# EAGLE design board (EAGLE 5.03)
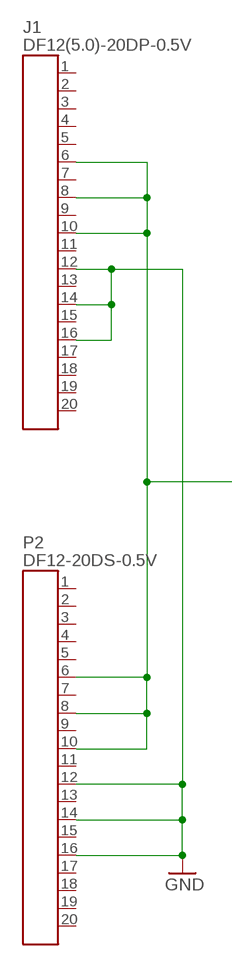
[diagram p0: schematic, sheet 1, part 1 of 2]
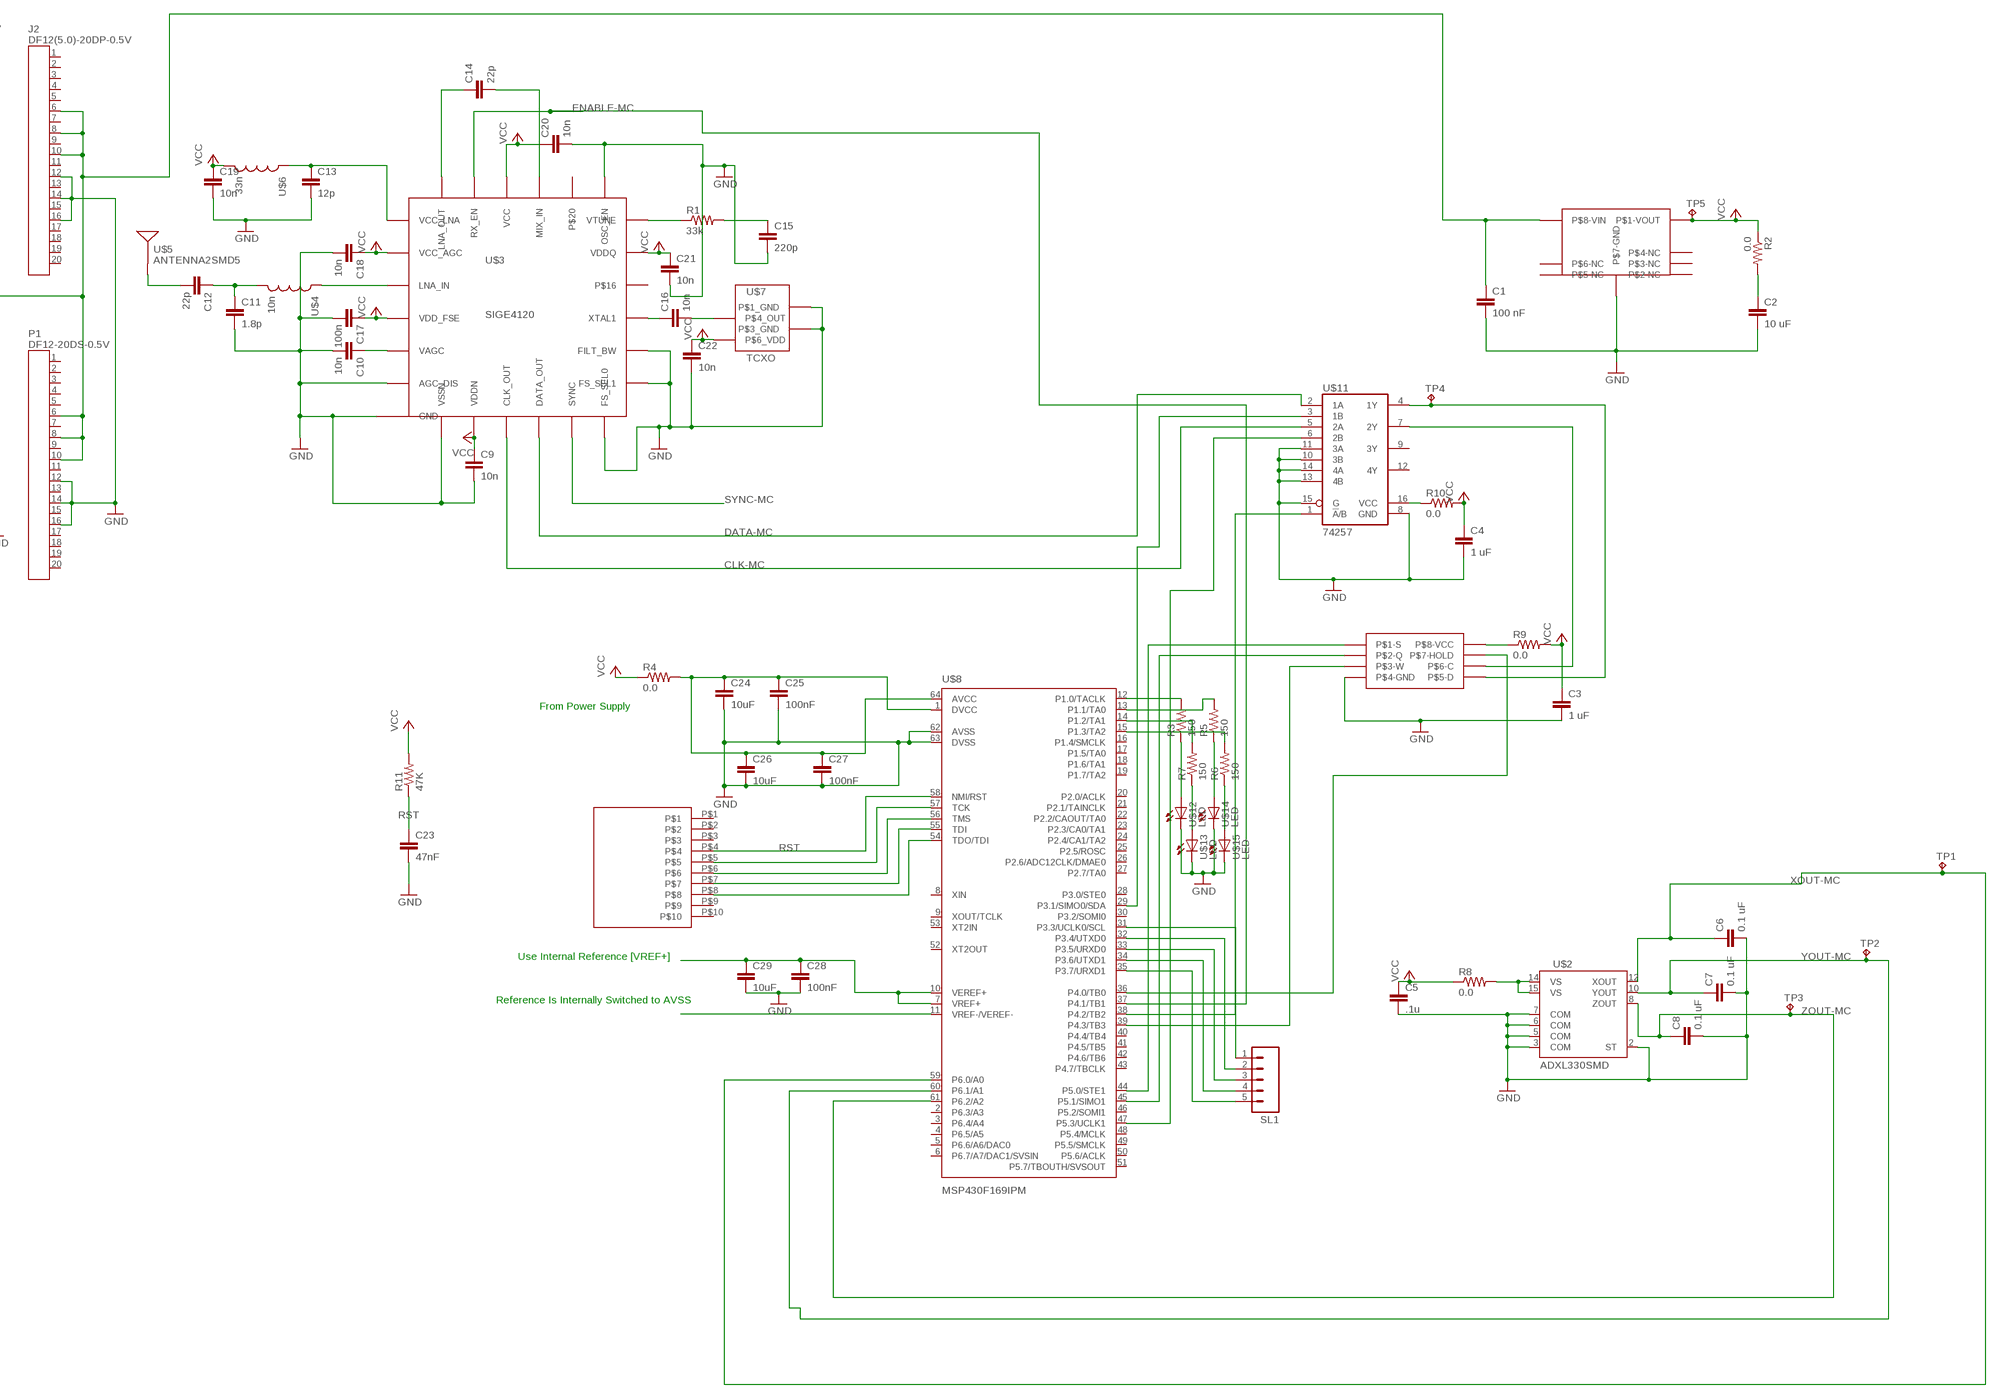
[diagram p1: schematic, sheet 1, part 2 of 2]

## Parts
C1  100 nF  CAP0402  [C0402]
C2  10 uF  CAP0402  [C0402]
C3  1 uF  CAP0402  [C0402]
C4  1 uF  CAP0402  [C0402]
C5  .1u  CAP0402  [C0402]
C6  0.1 uF  CAP0402  [C0402]
C7  0.1 uF  CAP0402  [C0402]
C8  0.1 uF  CAP0402  [C0402]
C9  10n  CAP0402  [C0402]
C10  10n  CAP0402  [C0402]
C11  1.8p  CAP0402  [C0402]
C12  22p  CAP0402  [C0402]
C13  12p  CAP0402  [C0402]
C14  22p  CAP0402  [C0402]
C15  220p  CAP0402  [C0402]
C16  10n  CAP0402  [C0402]
C17  100n  CAP0402  [C0402]
C18  10n  CAP0402  [C0402]
C19  10n  CAP0402  [C0402]
C20  10n  CAP0402  [C0402]
C21  10n  CAP0402  [C0402]
C22  10n  CAP0402  [C0402]
C23  47nF  CAP0402  [C0402]
C24  10uF  CAP0402  [C0402]
C25  100nF  CAP0402  [C0402]
C26  10uF  CAP0402  [C0402]
C27  100nF  CAP0402  [C0402]
C28  100nF  CAP0402  [C0402]
C29  10uF  CAP0402  [C0402]
J1  DF12(5.0)-20DP-0.5V  [DF12(XX)-20DP-0.5V]
J2  DF12(5.0)-20DP-0.5V  [DF12(XX)-20DP-0.5V]
P1  DF12-20DS-0.5V  [DF12-20DS-0.5V]
P2  DF12-20DS-0.5V  [DF12-20DS-0.5V]
R1  33k  RESISTOR0402  [C0402]
R2  0.0  RESISTOR  [0805]
R3  150  RESISTOR0402  [C0402]
R4  0.0  RESISTOR  [0805]
R5  150  RESISTOR0402  [C0402]
R6  150  RESISTOR0402  [C0402]
R7  150  RESISTOR0402  [C0402]
R8  0.0  RESISTOR  [0805]
R9  0.0  RESISTOR  [0805]
R10  0.0  RESISTOR  [0805]
R11  47K  RESISTOR0402  [C0402]
SL1  M05  [1X05]
TP1  TPTP09SQ  [TP09SQ]
TP2  TPTP09SQ  [TP09SQ]
TP3  TPTP09SQ  [TP09SQ]
TP4  TPTP09SQ  [TP09SQ]
TP5  TPTP09SQ  [TP09SQ]
U$1  FH12A-10S-0.5SH(55)  [FH12A-10S-0.5SH(55)]
U$2  ADXL330SMD  [LFCSP-16]
U$3  SIGE4120  [SIGE4120]
U$4  10n  INDUCTOR0402  [C0402]
U$5  ANTENNA2SMD5  [ANTENNA-CHIP5]
U$6  33n  INDUCTOR0402  [C0402]
U$7  TCXO  [TXCO]
U$8  MSP430F169IPM  [S-PQFP64-G64]
U$9  M25P128  [VDFPN8]
U$10  LM2936  [8-SOIC]
U$11  74257  [16]
U$12  LED  [LED0402]
U$13  LED  [LED0402]
U$14  LED  [LED0402]
U$15  LED  [LED0402]

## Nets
CLK-MC: U$3.CLK_OUT U$11.5(2A)
DATA-MC: U$3.DATA_OUT U$11.2(1A)
ENABLE-MC: U$3.RX_EN U$8.37(P4.1/TB1)
GND: C1.2 C2.2 C3.2 C4.2 C5.2 C6.2 C7.2 C8.2 C9.2 C10.2 C11.2 C13.2 C15.2 C17.2 C18.2 C19.2 C20.2 C21.2 C22.2 C23.2 C24.2 C25.2 C26.2 C27.2 C28.2 C29.2 J1.12 J1.14 J1.16 J2.12 J2.14 J2.16 P1.12 P1.14 P1.16 P2.12 P2.14 P2.16 U$2.2(ST) U$2.3(COM) U$2.5(COM) U$2.6(COM) U$2.7(COM) U$3.AGC_DIS U$3.FILT_BW U$3.FS_SEL0 U$3.FS_SEL1 U$3.GND U$3.OSC_EN U$3.VSSN U$7.P$1_GND U$7.P$3_GND U$8.62(AVSS) U$8.63(DVSS) U$9.P$4(P$4-GND) U$10.P$7-GND U$11.8(GND) U$11.10(3B) U$11.11(3A) U$11.13(4B) U$11.14(4A) U$11.15(G) U$12.P$2 U$13.P$2 U$14.P$2 U$15.P$2
N$1: U$8.36(P4.0/TB0) U$9.P$7(P$7-HOLD)
N$2: C28.1 C29.1 U$8.7(VREF+) U$8.10(VEREF+)
N$3: U$1.P$8 U$8.54(TDO/TDI)
N$4: SL1.1 U$8.31(P3.3/UCLK0/SCL)
N$5: C10.1 U$3.VAGC
N$6: SL1.2 U$8.32(P3.4/UTXD0)
N$7: U$3.LNA_IN U$4.1
N$8: C11.1 C12.1 U$4.2
N$9: C12.2 U$5.FEED(SIGNAL)
N$10: C13.1 U$3.VCC_LNA U$6.1
N$11: C14.1 U$3.LNA_OUT
N$12: C14.2 U$3.MIX_IN
N$13: R1.1 U$3.VTUNE
N$14: C15.1 R1.2
N$15: C16.1 U$3.XTAL1
N$16: C16.2 U$7.P$4_OUTPUT(P$4_OUT)
N$17: C1.1 J1.6 J1.8 J1.10 J2.6 J2.8 J2.10 P1.6 P1.8 P1.10 P2.6 P2.8 P2.10 U$10.P$8-VIN
N$18: C2.1 R2.2
N$19: U$8.11(VREF-/VEREF-)
N$20: SL1.3 U$8.33(P3.5/URXD0)
N$21: C24.1 C25.1 C26.1 C27.1 R4.2 U$8.1(DVCC) U$8.64(AVCC)
N$22: SL1.4 U$8.34(P3.6/UTXD1)
N$23: SL1.5 U$8.35(P3.7/URXD1)
N$24: U$8.45(P5.1/SIMO1) U$9.P$2(P$2-Q)
N$25: U$8.44(P5.0/STE1) U$9.P$1(P$1-S)
N$26: U$8.38(P4.2/TB2) U$11.1(!A!/B)
N$27: R9.1 U$9.P$8(P$8-VCC)
N$28: TP4.TP U$9.P$5(P$5-D) U$11.4(1Y)
N$29: U$8.47(P5.3/UCLK1) U$11.6(2B)
N$30: U$8.29(P3.1/SIMO0/SDA) U$11.3(1B)
N$31: U$1.P$7 U$8.55(TDI)
N$32: U$1.P$6 U$8.56(TMS)
N$33: U$1.P$5 U$8.57(TCK)
N$34: U$8.39(P4.3/TB3) U$9.P$3(P$3-W)
N$35: R3.2 U$8.12(P1.0/TACLK)
N$36: U$9.P$6(P$6-C) U$11.7(2Y)
N$37: R3.1 U$12.P$1
N$38: R5.2 U$8.13(P1.1/TA0)
N$39: R5.1 U$14.P$1
N$40: R7.2 U$8.14(P1.2/TA1)
N$41: R7.1 U$13.P$1
N$42: R6.2 U$8.15(P1.3/TA2)
N$43: R6.1 U$15.P$1
N$44: R8.2 U$2.14(VS) U$2.15(VS)
N$45: R10.1 U$11.16(VCC)
RST: C23.1 R11.1 U$1.P$4 U$8.58(NMI/RST)
SYNC-MC: U$3.SYNC
VCC: C3.1 C4.1 C5.1 C9.1 C17.1 C18.1 C19.1 C20.1 C21.1 C22.1 R2.1 R4.1 R8.1 R9.2 R10.2 R11.2 TP5.TP U$3.VCC U$3.VCC_AGC U$3.VDD_FSE U$3.VDDN U$3.VDDQ U$6.2 U$7.P$6_VDD U$10.P$1-VOUT
XOUT-MC: C6.1 TP1.TP U$2.12(XOUT) U$8.59(P6.0/A0)
YOUT-MC: C7.1 TP2.TP U$2.10(YOUT) U$8.60(P6.1/A1)
ZOUT-MC: C8.1 TP3.TP U$2.8(ZOUT) U$8.61(P6.2/A2)
Unconnected: J1.1 J1.2 J1.3 J1.4 J1.5 J1.7 J1.9 J1.11 J1.13 J1.15 J1.17 J1.18 J1.19 J1.20 J2.1 J2.2 J2.3 J2.4 J2.5 J2.7 J2.9 J2.11 J2.13 J2.15 J2.17 J2.18 J2.19 J2.20 P1.1 P1.2 P1.3 P1.4 P1.5 P1.7 P1.9 P1.11 P1.13 P1.15 P1.17 P1.18 P1.19 P1.20 P2.1 P2.2 P2.3 P2.4 P2.5 P2.7 P2.9 P2.11 P2.13 P2.15 P2.17 P2.18 P2.19 P2.20 U$1.P$1 U$1.P$2 U$1.P$3 U$1.P$9 U$1.P$10 U$3.P$16 U$3.P$20 U$8.2(P6.3/A3) U$8.3(P6.4/A4) U$8.4(P6.5/A5) U$8.5(P6.6/A6/DAC0) U$8.6(P6.7/A7/DAC1/SVSIN) U$8.8(XIN) U$8.9(XOUT/TCLK) U$8.16(P1.4/SMCLK) U$8.17(P1.5/TA0) U$8.18(P1.6/TA1) U$8.19(P1.7/TA2) U$8.20(P2.0/ACLK) U$8.21(P2.1/TAINCLK) U$8.22(P2.2/CAOUT/TA0) U$8.23(P2.3/CA0/TA1) U$8.24(P2.4/CA1/TA2) U$8.25(P2.5/ROSC) U$8.26(P2.6/ADC12CLK/DMAE0) U$8.27(P2.7/TA0) U$8.28(P3.0/STE0) U$8.30(P3.2/SOMI0) U$8.40(P4.4/TB4) U$8.41(P4.5/TB5) U$8.42(P4.6/TB6) U$8.43(P4.7/TBCLK) U$8.46(P5.2/SOMI1) U$8.48(P5.4/MCLK) U$8.49(P5.5/SMCLK) U$8.50(P5.6/ACLK) U$8.51(P5.7/TBOUTH/SVSOUT) U$8.52(XT2OUT) U$8.53(XT2IN) U$10.P$2-NC U$10.P$3-NC U$10.P$4-NC U$10.P$5-NC U$10.P$6-NC U$11.9(3Y) U$11.12(4Y)

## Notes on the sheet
- From Power Supply
- Use Internal Reference [VREF+]
- Reference Is Internally Switched to AVSS

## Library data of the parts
C1-C29 = SparkFun:CAP: Capacitor
J1 J2 = Hirose Connectors:DF12(5.0)-20DP-0.5V: Connector, Header, board-board, 20-pin. Dual Row, 5mm stack height, 0.5mm Pitch (Hirose)
P1 P2 = Hirose Connectors:DF12-20DS-0.5V: Connector, Receptacle, board-board, 20-pin. Dual Row, 3.5 to 5mm stack height, 0.5mm Pitch (Hirose)
R1-R11 = SparkFun:RESISTOR: Resistor
SL1 = SparkFun-3-2-07:M05: Header 5 Standard 5-pin 0.1" header. Use with straight break away headers (SKU : PType-HD), right angle break away headers (PType-HD-RightAngle), swiss pins (PType-30F), machine pins (PType-MP), and female headers (PType-FH). Molex polarized connector foot print use with SKU : Con-Hdr with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
TP1-TP5 = testpad:TP: Test pad
U$1 = mylib:FH12A-10S-0.5SH(55)
U$2 = SparkFun:ADXL330: Triple Axis Accelerometer Analog Devices ADXL330 +/-3g 2.4V-5.25V Analog output. Spark Fun Electronics SKU : COM-00730. Center pad paste layer has been reduced to avoid shorting.
U$3 = mylib:SIGE4120
U$4 U$6 = SparkFun:INDUCTOR: Inductors
U$5 = SparkFun:ANTENNA2: Antenna
U$7 = mylib:TCXO
U$8 = msp430:MSP430F16*: Mixed Signal Microcontroller 12bit ADC, 12bit DAC, I²C, USART, no LCD
U$9 = mylib:M25P128
U$10 = lm2936a:LM2936
U$11 = mylib:74257
U$12-U$15 = mylib:LED

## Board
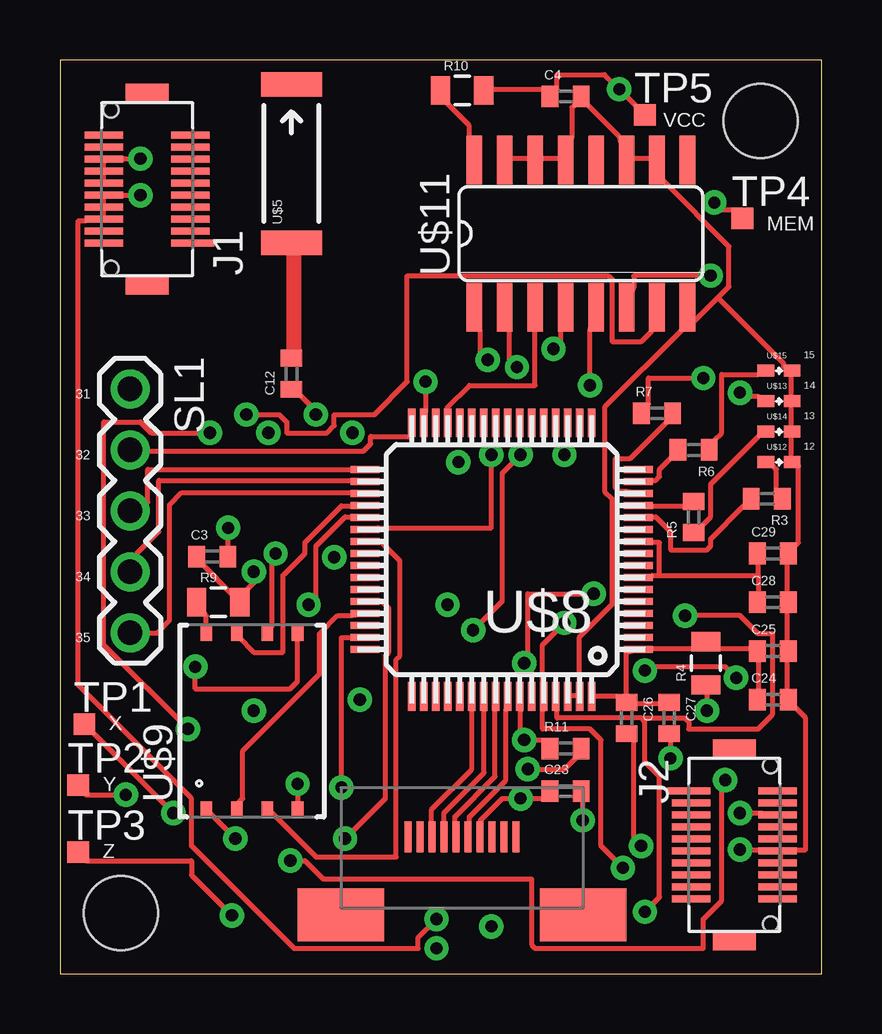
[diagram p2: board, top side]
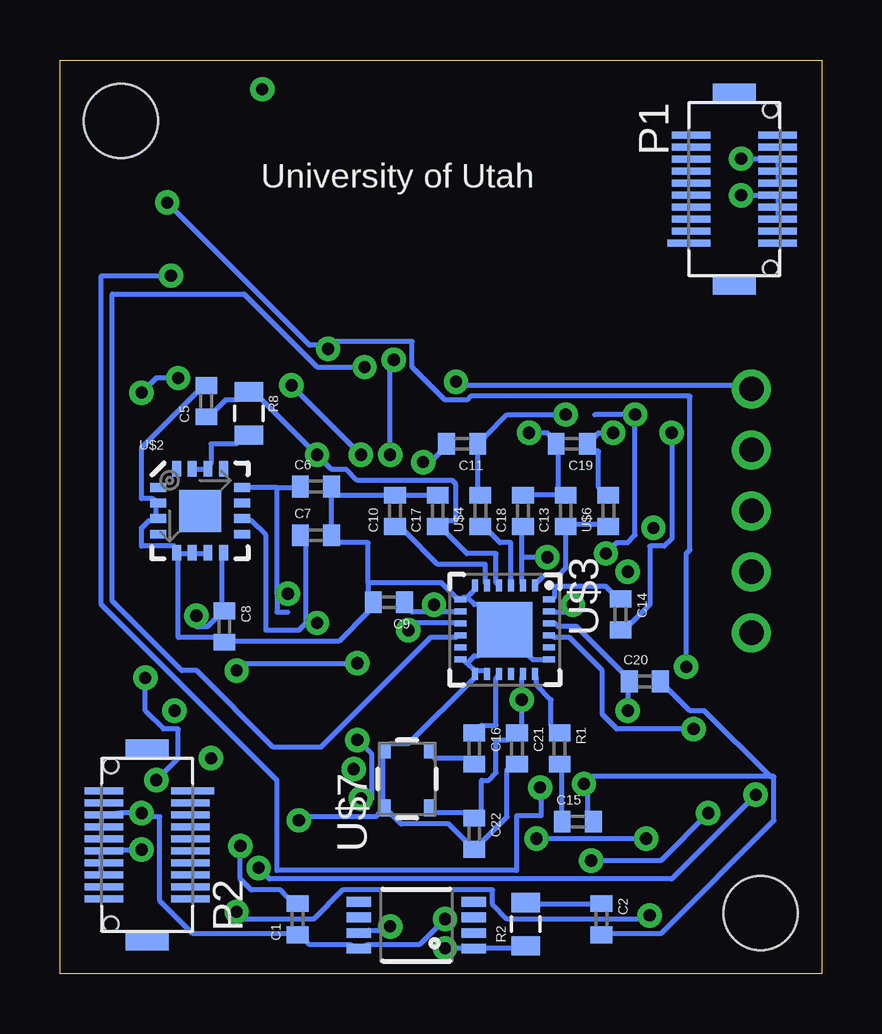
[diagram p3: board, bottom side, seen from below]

Size 31.75 x 38.1 mm. Coordinates in mm from the lower left corner, seen from the top.
Outline: 0,0 31.75,0 31.75,38.1 0,38.1 0,0
Copper layers ((1*2)+(15*16)): Top 0.035mm / dielectric 1.5mm / $gnd 0.035mm / dielectric 0.15mm / $vcc 0.035mm / dielectric 0.2mm / Bottom 0.035mm
Design rules "SparkFun *": minimum track width 8mil, minimum drill 20mil, track to track 6mil, track to pad 6mil, pad to pad 6mil, via to via 6mil, smd to smd 6mil, copper to edge 10mil, drill to drill 8mil, minimum pad ring 12mil, minimum via ring 10mil, stop-mask expansion 4mil, vias tented up to drill 25mil, thermal gap 10mil
Holes 3.1 mm at 2.54,2.54 29.21,35.56
tRestrict: 4 lines
bRestrict: 4 lines

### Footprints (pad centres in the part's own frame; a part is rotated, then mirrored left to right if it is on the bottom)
C0402 = smd 0.7 x 0.9: 1 -0.65,0; 2 0.65,0
DF12(XX)-20DP-0.5V = smd 0.3 x 1.8: 1 -2.25,-1.9 | smd 0.3 x 1.6: 2 -2.25,1.8; 3 -1.75,-1.8; 4 -1.75,1.8; 5 -1.25,-1.8; 6 -1.25,1.8; 7 -0.75,-1.8; 8 -0.75,1.8; 9 -0.25,-1.8; 10 -0.25,1.8; 11 0.25,-1.8; 12 0.25,1.8; 13 0.75,-1.8; 14 0.75,1.8; 15 1.25,-1.8; 16 1.25,1.8; 17 1.75,-1.8; 18 1.75,1.8; 19 2.25,-1.8; 20 2.25,1.8 | smd 0.8 x 1.8: T1 4,0; T2 -4,0 | hole 0.635: 3.3,1.5; -3.3,1.5
DF12-20DS-0.5V = smd 0.3 x 1.8: 1 2.25,-1.9 | smd 0.3 x 1.6: 2 2.25,1.8; 3 1.75,-1.8; 4 1.75,1.8; 5 1.25,-1.8; 6 1.25,1.8; 7 0.75,-1.8; 8 0.75,1.8; 9 0.25,-1.8; 10 0.25,1.8; 11 -0.25,-1.8; 12 -0.25,1.8; 13 -0.75,-1.8; 14 -0.75,1.8; 15 -1.25,-1.8; 16 -1.25,1.8; 17 -1.75,-1.8; 18 -1.75,1.8; 19 -2.25,-1.8; 20 -2.25,1.8 | smd 0.8 x 1.8: T1 4,0; T2 -4,0 | hole 0.635: 3.3,1.5; -3.3,1.5
0805 = smd 0.8 x 1.2: 1 -0.9,0; 2 0.9,0
1X05 = drill 1.016 round: 1 0,0; 2 2.54,0; 3 5.08,0; 4 7.62,0; 5 10.16,0
TP09SQ = smd 0.9 x 0.9: TP 0,0
FH12A-10S-0.5SH(55) = smd 0.3 x 1.3: P$1 -2.25,0; P$2 -1.75,0; P$3 -1.25,0; P$4 -0.75,0; P$5 -0.25,0; P$6 0.25,0; P$7 0.75,0; P$8 1.25,0; P$9 1.75,0; P$10 2.25,0 | smd 3.6 x 2.2: P$11 -5.05,3.25; P$12 5.05,3.25
LFCSP-16 = smd 1.75 x 1.75: 0 0,0 | smd 0.65 x 0.37: 1 -1.75,0.975; 2 -1.75,0.325; 3 -1.75,-0.325; 4 -1.75,-0.975; 9 1.75,-0.975; 10 1.75,-0.325; 11 1.75,0.325; 12 1.75,0.975 | smd 0.37 x 0.65: 5 -0.975,-1.75; 6 -0.325,-1.75; 7 0.325,-1.75; 8 0.975,-1.75; 13 0.975,1.75; 14 0.325,1.75; 15 -0.325,1.75; 16 -0.975,1.75
SIGE4120 = smd 0.5 x 0.25: AGC_DIS -1.85,-1.25; FILT_BW 1.85,-0.75; FS_SEL1 1.85,-1.25; LNA_IN -1.85,0.25; P$16 1.85,0.25; VAGC -1.85,-0.75; VCC_AGC -1.85,0.75; VCC_LNA -1.85,1.25; VDD_FSE -1.85,-0.25; VDDQ 1.85,0.75; VTUNE 1.85,1.25; XTAL1 1.85,-0.25 | smd 0.25 x 0.5: CLK_OUT -0.25,-1.85; DATA_OUT 0.25,-1.85; FS_SEL0 1.25,-1.85; LNA_OUT -1.25,1.85; MIX_IN 0.25,1.85; OSC_EN 1.25,1.85; P$20 0.75,1.85; RX_EN -0.75,1.85; SYNC 0.75,-1.85; VCC -0.25,1.85; VDDN -0.75,-1.85; VSSN -1.25,-1.85 | smd 2.3 x 2.3: GND 0,0
ANTENNA-CHIP5 = smd 1.016 x 2.54: FEED -3.302,0; NC 3.302,0
TXCO = smd 0.7 x 0.5: P$1_GND -1.2,0.95; P$3_GND 1.2,0.95; P$4_OUTPUT 1.2,-0.95; P$6_VDD -1.2,-0.95
S-PQFP64-G64 = smd 1.2 x 0.3: 1 -5.7,3.75; 2 -5.7,3.25; 3 -5.7,2.75; 4 -5.7,2.25; 5 -5.7,1.75; 6 -5.7,1.25; 7 -5.7,0.75; 8 -5.7,0.25; 9 -5.7,-0.25; 10 -5.7,-0.75; 11 -5.7,-1.25; 12 -5.7,-1.75; 13 -5.7,-2.25; 14 -5.7,-2.75; 15 -5.7,-3.25; 16 -5.7,-3.75; 33 5.7,-3.75; 34 5.7,-3.25; 35 5.7,-2.75; 36 5.7,-2.25; 37 5.7,-1.75; 38 5.7,-1.25; 39 5.7,-0.75; 40 5.7,-0.25; 41 5.7,0.25; 42 5.7,0.75; 43 5.7,1.25; 44 5.7,1.75; 45 5.7,2.25; 46 5.7,2.75; 47 5.7,3.25; 48 5.7,3.75 | smd 0.3 x 1.2: 17 -3.75,-5.7; 18 -3.25,-5.7; 19 -2.75,-5.7; 20 -2.25,-5.7; 21 -1.75,-5.7; 22 -1.25,-5.7; 23 -0.75,-5.7; 24 -0.25,-5.7; 25 0.25,-5.7; 26 0.75,-5.7; 27 1.25,-5.7; 28 1.75,-5.7; 29 2.25,-5.7; 30 2.75,-5.7; 31 3.25,-5.7; 32 3.75,-5.7; 49 3.75,5.7; 50 3.25,5.7; 51 2.75,5.7; 52 2.25,5.7; 53 1.75,5.7; 54 1.25,5.7; 55 0.75,5.7; 56 0.25,5.7; 57 -0.25,5.7; 58 -0.75,5.7; 59 -1.25,5.7; 60 -1.75,5.7; 61 -2.25,5.7; 62 -2.75,5.7; 63 -3.25,5.7; 64 -3.75,5.7
VDFPN8 = smd 0.6 x 0.48: P$1 -3.65,1.905; P$2 -3.65,0.635; P$3 -3.65,-0.635; P$4 -3.65,-1.905; P$5 3.65,-1.905; P$6 3.65,-0.635; P$7 3.65,0.635; P$8 3.65,1.905
8-SOIC = smd 0.41 x 1.02: P$1-VOUT -0.975,-2.4; P$2-NC -0.325,-2.4; P$3-NC 0.325,-2.4; P$4-NC 0.975,-2.4; P$5-NC 0.975,2.4; P$6-NC 0.325,2.4; P$7-GND -0.325,2.4; P$8-VIN -0.975,2.4
16 = smd 0.66 x 2.032: 1 -4.445,-3.073; 2 -3.175,-3.073; 3 -1.905,-3.073; 4 -0.635,-3.073; 5 0.635,-3.073; 6 1.905,-3.073; 7 3.175,-3.073; 8 4.445,-3.073; 9 4.445,3.073; 10 3.175,3.073; 11 1.905,3.073; 12 0.635,3.073; 13 -0.635,3.073; 14 -1.905,3.073; 15 -3.175,3.073; 16 -4.445,3.073
LED0402 = smd 0.7 x 0.5: P$1 -0.55,0; P$2 0.55,0

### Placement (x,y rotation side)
C1  21.84,2.29 90 bottom
C2  9.18,2.29 270 bottom
C3  6.35,17.4 0 top
C4  21.08,36.58 0 top
C5  25.65,23.88 90 bottom
C6  21.08,20.32 0 bottom
C7  21.08,18.29 0 bottom
C8  24.89,14.48 270 bottom
C9  18.03,15.49 180 bottom
C10  17.78,19.3 90 bottom
C11  14.99,22.1 180 bottom
C12  9.65,25.02 90 top
C13  10.67,19.3 90 bottom
C14  8.38,14.99 270 bottom
C15  10.16,6.35 0 bottom
C16  14.48,9.4 270 bottom
C17  16,19.3 90 bottom
C18  12.45,19.3 90 bottom
C19  10.41,22.1 180 bottom
C20  7.37,12.19 0 bottom
C21  12.7,9.4 270 bottom
C22  14.48,5.84 270 bottom
C23  21.08,7.62 0 top
C24  29.72,11.43 0 top
C25  29.72,13.46 0 top
C26  23.62,10.67 270 top
C27  25.4,10.67 270 top
C28  29.72,15.49 0 top
C29  29.72,17.53 0 top
J1  3.63,32.72 90 top
J2  28.12,5.38 270 top
P1  3.63,32.72 270 bottom
P2  28.12,5.38 90 bottom
R1  10.92,9.4 270 bottom
R2  12.33,2.08 90 bottom
R3  29.46,19.81 180 top
R4  26.92,12.95 90 top
R5  26.42,19.05 90 top
R6  26.42,21.84 180 top
R7  24.89,23.37 0 top
R8  23.88,23.37 270 bottom
R9  6.6,15.49 0 top
R10  16.76,36.83 0 top
R11  21.08,9.4 0 top
SL1  2.92,24.38 270 top
TP1  1.02,10.41 0 top
TP2  0.76,7.87 0 top
TP3  0.76,5.08 0 top
TP4  28.45,31.5 0 top
TP5  24.38,35.81 0 top
U$1  16.76,5.71 180 top
U$2  25.91,19.3 0 bottom
U$3  13.21,14.35 270 bottom
U$4  14.22,19.3 90 bottom
U$5  9.65,33.78 90 top
U$6  8.89,19.3 90 bottom
U$7  17.27,8.13 90 bottom
U$8  18.41,17.27 180 top
U$9  8,10.54 90 top
U$10  16.89,2.03 90 bottom
U$11  21.72,30.86 0 top
U$12  29.97,21.34 0 top
U$13  29.97,23.88 0 top
U$14  29.97,22.61 0 top
U$15  29.97,25.15 0 top

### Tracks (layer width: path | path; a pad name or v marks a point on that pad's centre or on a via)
CLK-MC  (via drill 0.51)
  Top 0.203: v17.22,14.33 18.44,15.54 18.44,20.88 v19.2,21.64 | v22.1,24.54 22.1,26.82 U$11.5
  Bottom 0.203: v17.22,14.33 16.92,14.63 15.24,14.63 U$3.CLK_OUT | v19.2,21.64 v22.1,24.54
DATA-MC  (via drill 0.51)
  Top 0.203: v19.05,25.3 18.75,25.6 18.75,26.82 U$11.2
  Bottom 0.203: v19.05,25.3 21.03,25.3 24.08,28.35 29.57,28.35 29.57,15.54 26.67,12.65 26.06,12.65 22.86,9.45 20.88,9.45 16.31,14.02 15.24,14.02 U$3.DATA_OUT
ENABLE-MC  (via drill 0.51)
  Top 0.203: v10.36,15.39 10.67,15.7 10.67,17.83 11.89,19.05 12.19,19.05 U$8.37
  Bottom 0.203: U$3.RX_EN 11.12,15.09 10.36,15.09 v10.36,15.39
GND  (via drill 0.51)
  Top 0.203: U$11.15 18.75,33.98 19.51,33.98 U$11.14 20.12,33.98 20.88,33.98 U$11.13 21.34,34.9 21.34,36.12 21.49,36.27 C4.2 21.95,36.27 23.32,34.9 U$11.11 23.93,33.98 24.69,33.98 U$11.10 25.15,33.07 27.89,30.33 27.89,28.65 27.43,28.19 | U$8.62 21.18,11.58 21.64,11.58 U$8.63 21.64,12.04 21.64,14.02 23.01,15.39 23.01,19.81 22.71,20.12 22.71,23.62 25.91,26.82 U$11.8 26.36,27.13 27.43,28.19 | P2.16 30.02,4.27 30.02,4.57 P2.14 30.02,4.72 30.02,5.03 P2.12 | P2.12 30.63,5.18 31.09,5.18 31.09,10.67 30.63,11.12 C24.2 30.33,11.73 30.33,13.11 C25.2 30.33,13.87 30.33,15.09 C28.2 30.33,15.85 30.33,17.22 C29.2 30.63,17.83 30.79,17.98 30.79,21.18 U$12.P$2 30.48,21.49 30.48,22.4 U$14.P$2 30.48,22.71 30.48,23.77 U$13.P$2 30.48,24.08 30.48,24.99 U$15.P$2 30.18,25.3 30.18,25.45 27.43,28.19 | J1.12 1.83,33.07 1.83,33.38 J1.14 1.83,33.53 1.83,33.83 J1.16 2.59,33.98 v3.35,33.98 | v9.91,7.92 U$9.P$4 | v7.01,18.59 7.01,17.83 C3.2 | v21.79,6.4 21.79,7.32 C23.2 | C26.2 23.93,9.75 23.93,5.64 v24.23,5.33 | v25.45,8.99 25.45,9.75 C27.2 | P2.12 29.26,5.18 v28.35,5.18
  Bottom 0.203: U$2.7 25.76,17.53 26.06,17.53 U$2.6 26.36,17.53 26.82,17.53 U$2.5 | U$2.5 26.98,17.83 28.35,17.83 28.35,18.59 28.04,18.9 27.89,18.9 U$2.3 27.74,19.05 27.74,19.51 U$2.2 27.89,19.81 28.35,19.81 28.35,21.95 26.06,24.23 C5.2 | 14.48,12.65 14.02,12.65 U$3.FILT_BW | 14.48,12.65 14.78,12.95 | 14.78,12.95 14.94,13.11 U$3.FS_SEL0 | 14.48,12.65 U$3.FS_SEL1 14.48,12.34 17.22,9.6 17.98,9.6 U$7.P$3_GND 18.29,8.99 18.29,7.16 U$7.P$1_GND | 14.78,15.7 14.48,16 U$3.AGC_DIS | 14.78,15.7 14.94,15.7 U$3.VSSN 15.24,15.7 15.85,16.31 18.9,16.31 | U$3.OSC_EN 11.58,13.11 12.04,13.11 12.19,13.26 U$3.GND | 14.78,15.7 14.48,15.39 14.33,15.39 U$3.GND | 14.78,12.95 14.48,13.26 14.33,13.26 U$3.GND | C17.2 16.31,19.96 17.37,19.96 C10.2 18.14,19.96 20.12,19.96 C6.2 20.42,19.96 20.42,18.59 C7.2 20.12,17.98 18.9,17.98 18.9,16.31 | 18.9,16.31 18.9,15.85 C9.2 18.9,15.09 20.12,13.87 24.54,13.87 C8.2 25.3,14.02 26.82,14.02 26.82,17.37 U$2.5 | C21.2 13.11,8.53 13.11,6.55 14.17,5.49 C22.2 14.78,5.49 15.54,6.25 17.53,6.25 17.98,6.71 U$7.P$1_GND | C18.2 12.04,19.96 10.97,19.96 C13.2 10.97,20.27 10.97,21.79 C19.2 11.28,22.4 11.43,22.55 v12.19,22.55 | P2.16 30.02,4.27 30.02,4.57 P2.14 30.02,4.72 30.02,5.03 P2.12 29.26,5.18 v28.35,5.18 | J1.12 1.83,33.07 1.83,33.38 J1.14 1.83,33.53 1.83,33.83 J1.16 2.59,33.98 v3.35,33.98 | 2.13,8.23 9.6,8.23 v9.91,7.92 9.75,7.47 9.75,6.71 C15.2 | 2.13,8.23 1.98,8.23 1.98,6.4 6.71,1.68 8.84,1.68 C2.2 | 2.13,8.23 4.88,10.97 5.49,10.97 6.4,11.89 C20.2 | v24.23,5.33 24.23,3.96 23.77,3.5 22.55,3.5 22.25,3.2 C1.2 | v16.61,21.34 16.31,21.34 15.85,21.79 C11.2
  Bottom 0.203: v17.98,1.98 18.14,1.83 18.9,1.83 U$10.P$7-GND | U$7.P$1_GND 18.44,6.71 18.59,6.55 21.34,6.55 v21.79,6.4
N$1
  Top 0.203: U$9.P$7 7.47,14.02 8.08,13.41 9.3,13.41 9.3,16.61 10.21,17.53 10.21,17.98 11.73,19.51 12.19,19.51 U$8.36
N$2
  Top 0.203: 29.11,16.61 29.11,17.22 C29.1 | 29.11,16.61 29.11,15.85 C28.1 | 24.99,16.61 29.11,16.61 | 24.99,16.61 24.69,16.61 U$8.7 | 24.99,16.61 24.99,17.98 24.69,17.98 U$8.10
N$3
  Top 0.203: U$8.54 17.17,8.53 15.49,6.86 15.49,5.74 U$1.P$8
N$4  (via drill 0.51)
  Top 0.203: v15.24,24.69 15.24,23.47 U$8.31
  Bottom 0.203: v15.24,24.69 15.09,24.54 3.66,24.54 SL1.1
N$5
  Bottom 0.203: U$3.VAGC 14.02,16.31 14.02,17.07 16,17.07 17.37,18.44 C10.1
N$6
  Top 0.203: U$8.32 14.63,22.4 12.95,22.4 12.95,22.1 12.65,21.79 3.66,21.79 SL1.2
N$7
  Bottom 0.203: U$3.LNA_IN 12.95,16.31 12.95,17.98 13.41,17.98 13.87,18.44 U$4.1
N$8  (via drill 0.51)
  Top 0.203: v10.67,23.32 10.67,23.47 10.06,24.08 C12.1
  Bottom 0.203: U$4.2 14.33,20.27 14.33,21.79 C11.1 14.02,22.4 13.11,23.32 v10.67,23.32
N$9
  Top 0.203: C12.2 9.75,25.91 | 9.75,30.02 U$5.FEED
  Top 0.616: 9.75,25.91 9.75,30.02
N$10
  Bottom 0.203: U$3.VCC_LNA 11.89,16.31 11.58,16.61 10.97,16.61 10.67,16.92 C13.1 10.36,18.75 9.3,18.75 U$6.1
N$11
  Bottom 0.203: U$3.LNA_OUT 11.12,15.7 11.12,16.15 8.99,16.15 8.69,15.85 C14.1
N$12  (via drill 0.51)
  Top 0.203: v6.25,22.55 3.81,22.55 3.35,23.01 1.83,23.01 1.83,13.72 v5.33,10.21
  Bottom 0.203: U$3.MIX_IN 11.12,14.02 10.52,14.02 9.14,12.65 9.14,10.82 8.53,10.21 v5.33,10.21 | C14.2 8.08,14.63 7.92,14.63 7.16,15.39 7.16,17.83 6.55,17.83 6.25,18.14 v6.25,22.55
N$13
  Bottom 0.203: U$3.VTUNE 11.89,12.34 11.89,12.04 11.28,11.43 11.28,10.36 R1.1
N$14
  Bottom 0.203: C15.1 10.82,6.71 10.82,8.53 R1.2
N$15
  Bottom 0.203: U$3.XTAL1 13.56,12.34 13.56,10.36 14.17,10.36 C16.1
N$16
  Bottom 0.203: U$7.P$4_OUTPUT 16.15,8.99 14.78,8.99 C16.2
N$17  (via drill 0.51)
  Top 0.203: v3.35,32.46 2.59,32.46 P1.10 1.83,32 P1.8 1.83,31.85 1.83,31.55 P1.6 1.07,31.39 0.76,31.39 0.76,12.04 5.49,7.32 5.49,5.33 9.75,1.07 14.94,1.07 14.94,1.52 v15.7,2.29 | J2.10 30.02,5.64 30.02,6.1 J2.8 30.02,6.25 30.02,6.55 J2.6 29.26,6.71 v28.35,6.71
  Bottom 0.203: P1.6 1.83,31.55 1.83,31.85 P1.8 1.83,32 P1.10 2.59,32.46 v3.35,32.46 | J2.10 30.02,5.64 30.02,6.1 J2.8 30.02,6.25 30.02,6.55 J2.6 29.26,6.71 v28.35,6.71 27.89,6.55 27.58,6.55 27.58,3.05 26.21,1.68 22.25,1.68 C1.1 21.49,1.37 21.34,1.22 19.66,1.22 U$10.P$8-VIN 18.9,1.22 16.76,1.22 v15.7,2.29
N$18
  Bottom 0.203: C2.1 9.6,2.9 11.73,2.9 R2.2
N$20
  Top 0.203: U$8.33 12.19,21.03 3.66,21.03 3.66,19.66 SL1.3
N$21
  Top 0.203: C26.1 23.93,11.28 24.99,11.28 C27.1 | U$8.64 22.25,11.58 23.32,11.58 C26.1 | C24.1 29.11,11.73 29.11,13.11 C25.1 28.8,13.56 27.43,13.56 R4.2 26.36,13.56 24.69,13.56 U$8.1 23.62,13.41 C26.1
N$22
  Top 0.203: U$8.34 12.19,20.57 4.12,20.57 4.12,18.44 3.2,17.53 SL1.4
N$23
  Top 0.203: U$8.35 12.67,20.07 5.08,20.07 4.57,19.56 4.57,14.73 4.06,14.22 SL1.5
N$24
  Top 0.203: U$9.P$2 7.47,7.16 7.62,7.32 7.62,9.3 10.82,12.5 10.82,14.17 11.58,14.94 12.19,14.94 U$8.45
N$25  (via drill 0.51)
  Top 0.203: v7.32,5.64 6.25,6.71 U$9.P$1 | v11.89,5.64 13.56,7.32 13.56,13.26 13.72,13.41 13.72,15.24 13.41,15.54 13.26,15.54 U$8.44
  Bottom 0.203: v7.32,5.64 v11.89,5.64
N$26  (via drill 0.51)
  Top 0.203: v17.98,21.64 17.98,18.59 13.26,18.59 U$8.38 | v17.83,25.6 17.53,25.91 17.53,26.82 U$11.1
  Bottom 0.203: v17.98,21.64 17.98,25.6 v17.83,25.6
N$27
  Top 0.203: U$9.P$8 6.1,14.94 R9.1
N$28  (via drill 0.51)
  Top 0.203: v5.64,12.8 5.64,11.89 9.6,11.89 9.91,12.19 U$9.P$5 | v20.57,26.06 20.88,26.36 20.88,26.82 U$11.4 | v27.28,32.16 27.28,31.85 28.04,31.85 TP4.TP
  Bottom 0.203: v5.64,12.8 5.64,17.53 5.49,17.68 5.49,24.08 14.63,24.08 14.78,23.93 15.7,23.93 17.07,25.3 17.07,26.36 20.27,26.36 v20.57,26.06 21.03,26.21 21.34,26.21 v27.28,32.16
N$29  (via drill 0.51)
  Top 0.203: v11.73,7.77 11.73,14.02 12.19,14.02 U$8.47 | v27.13,29.11 23.93,29.11 23.93,28.65 U$11.6
  Bottom 0.203: v27.13,29.11 30.02,29.11 30.02,15.39 22.71,8.08 22.71,4.32 12.7,4.32 12.7,6.6 11.68,6.6 11.68,7.77 v11.73,7.77
N$30
  Top 0.203: U$8.29 16.15,23.47 16.15,23.62 17.07,24.54 19.81,24.54 U$11.3
N$31
  Top 0.203: U$8.55 17.68,10.97 17.68,8.38 16,6.71 16,6.25 U$1.P$7
N$32
  Top 0.203: U$8.56 18.14,10.97 18.14,8.23 16.46,6.55 16.46,6.25 U$1.P$6
N$33
  Top 0.203: U$8.57 18.59,10.97 18.59,8.08 17.07,6.55 17.07,6.25 U$1.P$5
N$34
  Top 0.203: U$9.P$3 8.84,6.71 10.67,4.88 14.02,4.88 14.02,13.11 14.17,13.26 14.17,17.22 13.41,17.98 13.26,17.98 U$8.39
N$35
  Top 0.203: R3.2 28.5,19.51 27.13,18.14 27.13,17.83 26.98,17.68 25.45,17.68 25.45,18.44 24.84,19.05 24.69,19.05 U$8.12
N$36  (via drill 0.51)
  Top 0.203: v8.99,17.53 8.84,17.37 8.84,14.48 U$9.P$6 | v7.77,23.32 9.14,23.32 9.45,23.01 9.45,22.55 11.12,22.55 11.43,22.86 11.43,23.32 13.11,23.32 14.48,24.69 14.48,29.11 22.86,29.11 23.01,28.96 23.01,26.36 24.23,26.36 24.69,26.82 U$11.7
  Bottom 0.203: 9.45,23.32 v7.77,23.32 7.77,18.29 8.08,17.98 8.53,17.98 v8.99,17.53
N$37
  Top 0.203: U$12.P$1 29.72,21.18 29.87,21.03 29.87,20.12 R3.1
N$38
  Top 0.203: R5.2 26.06,19.51 24.69,19.51 U$8.13
N$39
  Top 0.203: U$14.P$1 29.11,22.4 27.13,20.42 27.13,19.05 26.82,18.75 R5.1
N$40
  Top 0.203: R7.2 25.3,23.01 23.77,21.49 23.16,21.49 23.16,20.27 23.32,20.12 23.62,20.12 U$8.14
N$41  (via drill 0.51)
  Top 0.203: v28.35,24.23 28.35,24.08 29.11,24.08 U$13.P$1 | v26.82,24.84 24.54,24.84 24.54,23.77 R7.1
  Bottom 0.203: v28.35,24.23 27.74,24.84 v26.82,24.84
N$42
  Top 0.203: R6.2 25.45,21.49 24.99,21.03 24.99,20.73 24.84,20.57 24.69,20.57 U$8.15
N$43
  Top 0.203: U$15.P$1 29.11,24.99 27.58,24.99 27.58,22.55 27.28,22.25 R6.1
N$44
  Bottom 0.203: U$2.15 26.06,21.03 25.76,21.03 U$2.14 25.45,21.34 25.45,22.1 24.38,22.1 R8.2
N$45
  Top 0.203: R10.1 16.15,36.27 17.07,35.36 17.07,34.9 U$11.16
RST  (via drill 0.51)
  Top 0.203: R11.1 20.12,9.75 v19.36,9.75 19.2,9.75 19.2,10.97 U$8.58 | C23.1 20.12,7.32 v19.2,7.32 18.44,7.32 17.53,6.4 17.53,6.25 U$1.P$4
  Bottom 0.203: v19.36,9.75 18.75,9.14 18.75,7.32 v19.2,7.32
VCC  (via drill 0.51)
  Top 0.203: TP5.TP v23.32,36.88 22.71,37.49 20.73,37.49 20.73,36.88 C4.1 20.12,36.88 17.98,36.88 R10.2 | C3.1 5.94,17.07 7.16,15.85 R9.2 7.77,16 8.08,16.31 v8.08,16.76 | v19.51,8.53 21.03,8.53 21.49,8.99 R11.2 | v26.98,10.97 26.98,11.73 R4.1
  Bottom 0.203: C5.1 25.3,23.47 24.84,23.93 24.38,23.93 R8.1 23.32,23.93 v21.03,21.64 20.42,21.03 19.81,21.03 19.36,20.57 15.39,20.57 15.24,20.42 15.24,18.9 15.7,18.9 C17.1 15.7,18.44 14.78,17.53 13.56,17.53 13.56,16.31 U$3.VDD_FSE | U$7.P$6_VDD 16.15,6.71 14.78,6.71 C22.1 14.17,6.71 14.17,8.08 13.87,8.08 13.56,8.38 13.56,9.75 13.11,9.75 C21.1 12.5,10.36 v12.5,11.43 12.5,12.34 U$3.VDDQ | U$3.VCC 11.12,14.63 10.97,14.48 10.21,14.48 8.23,12.5 C20.1 8.08,11.89 v8.08,10.97 | U$6.2 9.3,20.27 9.3,21.79 9.45,21.79 C19.1 9.45,22.4 9.3,22.55 v8.69,22.55 | R2.1 12.8,1.07 14.02,1.07 U$10.P$1-VOUT 14.94,1.07 v15.7,1.07 | 12.5,17.37 12.5,18.44 C18.1 | 12.5,17.37 12.5,16.31 U$3.VCC_AGC | 16.15,15.09 17.07,15.09 C9.1 | 16.15,15.09 15.24,15.09 U$3.VDDN | 16.15,15.09 v16.15,15.39 | 12.5,17.37 v11.43,17.37
XOUT-MC  (via drill 0.51)
  Top 0.203: v9.6,4.72 10.21,4.72 10.97,3.96 19.66,3.96 19.66,1.22 19.81,1.07 26.82,1.07 26.82,2.29 27.58,3.05 27.58,7.92 v27.74,8.08 | v28.19,12.34 27.74,12.8 24.38,12.8 v24.38,12.65 | v4.72,6.71 TP1.TP | U$8.59 19.66,12.04 19.66,12.65 v19.36,12.95 19.51,13.41 19.51,15.85 v22.25,15.85
  Bottom 0.203: 22.71,20.27 21.95,20.27 C6.1 | 22.71,20.27 23.93,20.27 U$2.12 | 22.71,15.85 22.71,15.09 22.25,15.09 | 22.71,15.85 22.71,20.27 | v4.72,6.71 6.71,4.72 v9.6,4.72 | v27.74,8.08 26.82,8.99 26.82,10.21 27.43,10.21 28.19,10.97 v28.19,12.34 | v24.38,12.65 24.08,12.95 v19.36,12.95 | v22.25,15.85 22.71,15.85
YOUT-MC  (via drill 0.51)
  Top 0.203: v2.74,7.47 1.07,7.47 TP2.TP | v23.47,4.42 22.55,5.33 22.55,9.75 22.1,10.21 20.12,10.21 20.12,10.97 U$8.60 20.12,12.04 20.12,13.72 v21.03,14.63
  Bottom 0.203: 21.49,14.63 21.79,14.33 23.16,14.33 23.16,18.29 23.77,18.9 23.93,18.9 U$2.10 | 21.49,14.63 21.49,17.98 C7.1 | v2.74,7.47 6.25,3.96 23.01,3.96 v23.47,4.42 | v21.03,14.63 21.49,14.63
ZOUT-MC  (via drill 0.51)
  Top 0.203: v7.16,2.44 5.49,4.12 5.49,4.72 1.07,4.72 TP3.TP | v24.38,2.59 24.99,3.2 24.99,8.23 24.38,8.84 24.38,10.52 24.23,10.67 | 24.23,10.67 20.73,10.67 20.73,10.97 U$8.61 | v26.06,14.94 28.35,14.94 29.11,14.17 29.72,14.17 29.72,10.82 29.11,10.21 26.21,10.21 26.21,10.52 26.06,10.67 24.23,10.67
  Bottom 0.203: U$2.8 24.99,17.37 24.99,15.39 C8.1 25.3,14.78 25.6,14.48 26.06,14.48 v26.06,14.94 | v7.16,2.44 7.32,2.29 13.11,2.29 13.72,2.9 13.72,3.5 19.96,3.5 21.18,2.29 24.08,2.29 v24.38,2.59
(copper drawn outside any net)
  shapes: $gnd area x1, $vcc area x1

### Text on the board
tPlace: VCC | MEM | 15 | 31 | 14 | 13 | 32 | 12 | 33 | 34 | 35 | X | Y | Z
bPlace: University of Utah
